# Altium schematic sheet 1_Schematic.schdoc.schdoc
size 309 x 223 mm; Symbol: Sheet-Symbol_A4; Device: Sheet-Symbol_A4; @Project Name: USB-C Power Supply_kido; @Page Count: 1; @Update Date: 2024-03-10; @Create Date: 2024-03-10; @Schematic Name: USB-C Power Supply_kido; @Page No: 1; @Page Name: Schematic; Company: https://litt.ly/syskido; Reviewed: EasyEDA; Version: V0.1; Page Size: A4; Part Number: KIDO-0001; Drawn: syskido_kido
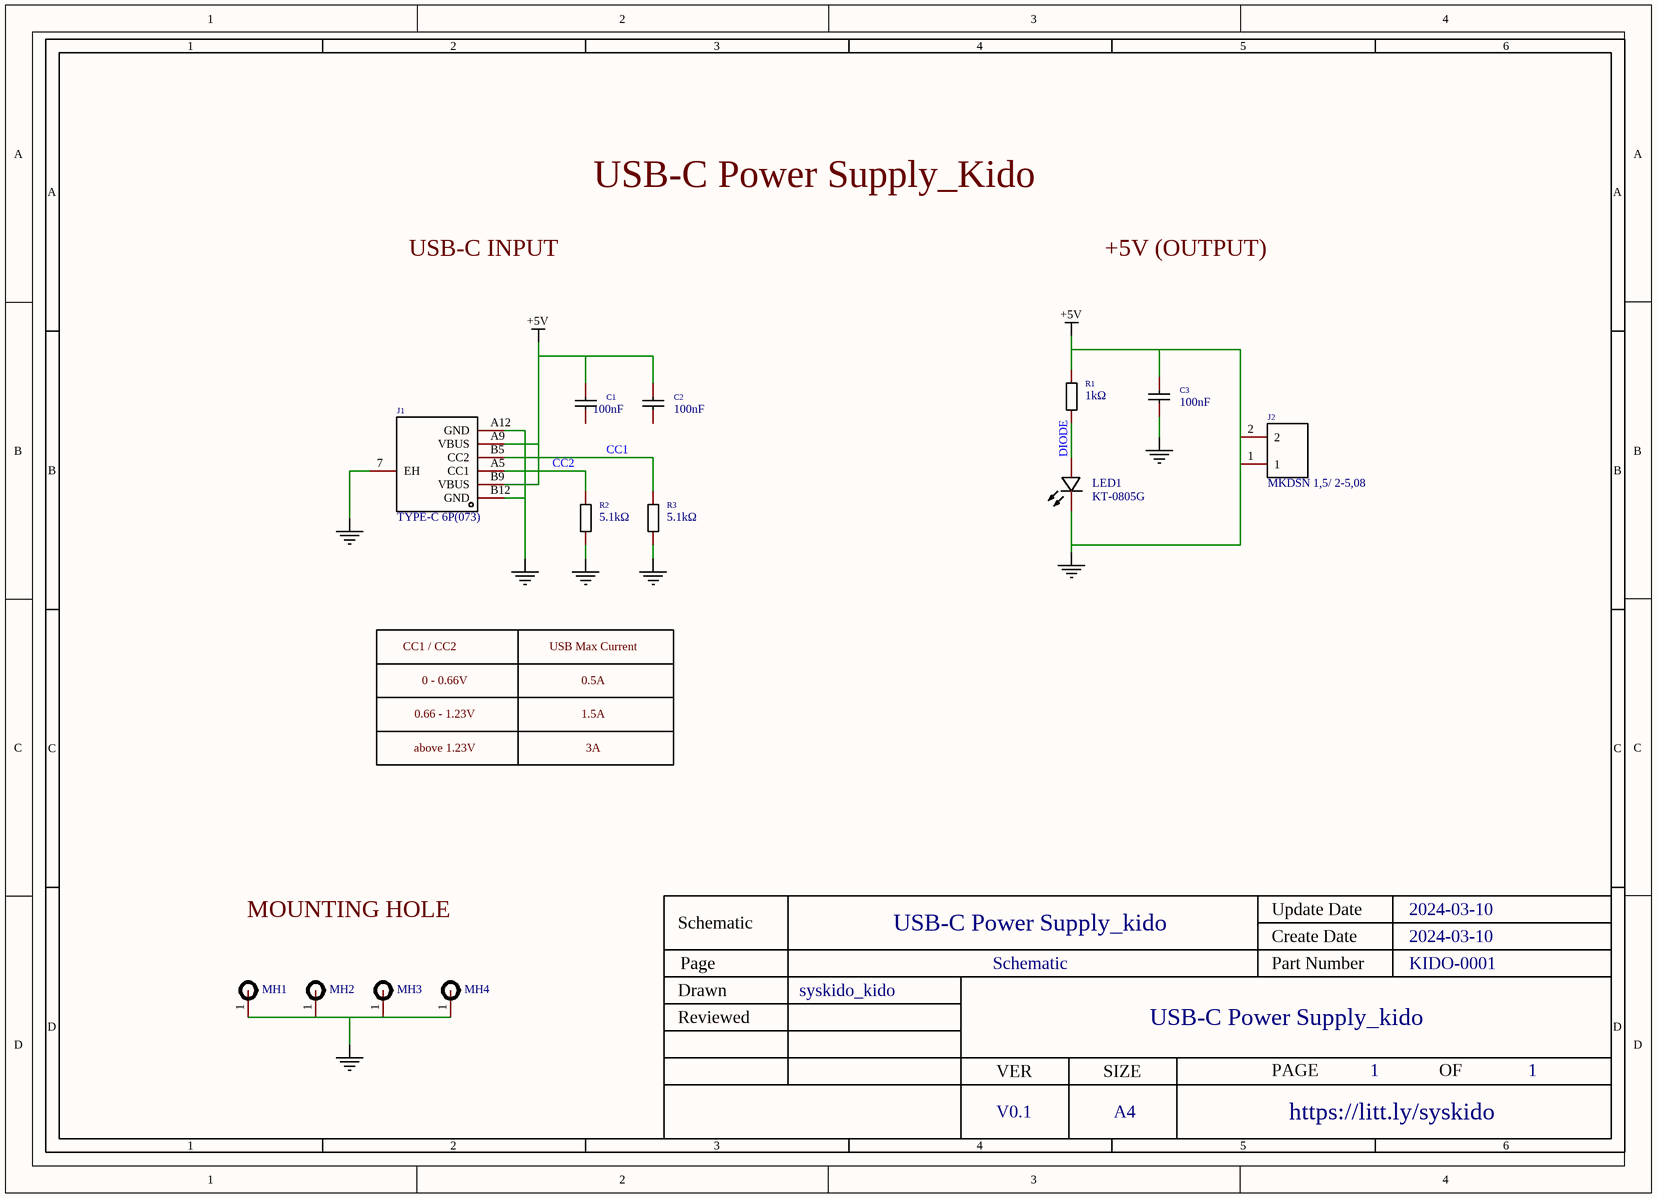
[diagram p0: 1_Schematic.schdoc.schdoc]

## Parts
C1  100nF  [C0805]
C2  100nF  [C0805]
C3  100nF  [C0805]
J1  TYPE-C 6P(073)  [TYPE-C-SMD_TYPE-C-6P]
J2  MKDSN 1,5/ 2-5,08  [CONN-TH_2P-P5.08_1729128]
LED1  KT-0805G  [LED0805-R-RD]
MH1  MH_7.5x2.7MM  [MH_7.5X2.7MM]  (value not drawn)
MH2  MH_7.5x2.7MM  [MH_7.5X2.7MM]  (value not drawn)
MH3  MH_7.5x2.7MM  [MH_7.5X2.7MM]  (value not drawn)
MH4  MH_7.5x2.7MM  [MH_7.5X2.7MM]  (value not drawn)
R1  1kΩ  [R0805]
R2  5.1kΩ  [R0805]
R3  5.1kΩ  [R0805]

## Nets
+5V: C1.2 C2.2 C3.2 J1.A9(VBUS) J1.B9(VBUS) J2.1 J2.2 LED1.2(K) R1.2
GND: C3.1 J1.7(EH) J1.A12(GND) J1.B12(GND) MH1.1 MH2.1 MH3.1 MH4.1 R2.1 R3.1
CC1: J1.B5(CC2) R3.2
CC2: J1.A5(CC1) R2.2
DIODE: LED1.1(A) R1.1

Not connected (* = marked no-connect by the designer): C1 1; C2 1

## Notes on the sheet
- USB-C Power Supply_Kido
- USB-C INPUT
- +5V (OUTPUT)
- CC1 / CC2
- 0 - 0.66V
- USB Max Current
- 0.5A
- 0.66 - 1.23V
- above 1.23V
- 1.5A
- 3A
- MOUNTING HOLE

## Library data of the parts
C1-C3 = CC0805KRX7R9BB104: Manufacturer: YAGEO(国巨); Add into BOM: yes; Tolerance: ±10%; Description: Capacitance: Tolerance:±10% Tolerance:±10% Voltage Rated: Temperature Coefficient:
J1 = TYPE-C 6P(073): Manufacturer: SHOU HAN(首韩); Add into BOM: yes; Gender: Female; Number of Ports: 1; Current Rating - Power (Max): 5A; Description: Connector Type:Type-C Standard:- Gender:Female Number of Ports:1 Number of Contacts:6P Mounting Style:卧贴 Current Rating - Power (Max):5A Operating Temperature Range:-25℃~+85℃ Operating Temperature Range:-25℃~+85℃
J2 = MKDSN 1,5/ 2-5,08: Manufacturer: Phoenix Contact(菲尼克斯); Add into BOM: yes
LED1 = KT-0805G: Manufacturer: KENTO; Symbol: 0805G (Green); Add into BOM: yes; Emitted Color: Emerald; Description: Lamp Holder Type:- Emitted Color:Emerald Forward Voltage (VF):- Forward Voltage (VF):- Power Dissipation:- Forward Current:- Dominant Wavelength:- Dominant Wavelength:- Peak Wavelength:- Diode Configuration:- Lens Color:- Color Temperature:- Color Tempera
MH1-MH4 = MH_7.5x2.7MM: Add into BOM: no; Convert to PCB: yes
R1 = 0805W8F1001T5E: Manufacturer: UNI-ROYAL(厚声); Add into BOM: yes; Tolerance: ±1%; Temperature Coefficient: ±100ppm/℃; Description: Type:Thick Film Resistors Resistance:1kΩ Tolerance:±1% Tolerance:±1% Power(Watts): Overload Voltage (Max): Temperature Coefficient:±100ppm/℃ Temperature Coefficient:±100ppm/℃ Operating Temperature Range:-55℃~+155℃ Operating Temperature Range:-55℃~+155℃
R2 R3 = 0805W8F5101T5E: Manufacturer: UNI-ROYAL(厚声); Add into BOM: yes; Tolerance: ±1%; Temperature Coefficient: ±100ppm/℃; Description: Type:Thick Film Resistors Resistance:5.1kΩ Tolerance:±1% Tolerance:±1% Power(Watts): Overload Voltage (Max): Temperature Coefficient:±100ppm/℃ Temperature Coefficient:±100ppm/℃ Operating Temperature Range:-55℃~+155℃ Operating Temperature Range:-55℃~+155℃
